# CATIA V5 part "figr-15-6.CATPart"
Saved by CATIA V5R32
Part number: Part1
Bounding box of the stored display mesh (mm): x -50 to 50, y -32.5 to 33.5, z -52 to 1
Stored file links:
  D:\PROJECTS\Project 2022\CATIA V5 6R 2022\Resources\Part Files\c15_catia_v5_6r2022_prt\figr-15-6.CATPart
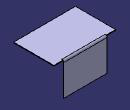
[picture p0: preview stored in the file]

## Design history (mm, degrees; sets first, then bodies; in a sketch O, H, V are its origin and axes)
SheetMetalParameters1: Thickness 1, BendRadius 2, KFactor 0.400515 {= log(min(100,max(20*SheetMetalParameters1.BendRadius,SheetMetalParameters1.Thickness)/SheetMetalParameters1.Thickness))/log(100)/2}, ReliefRadialLength 1, ReliefAxialLength 2, MinimumBendRadius 0
Body1 (main body)
  Sketch1 on xy-plane, origin (0, 0, 0), H (1, 0, 0), V (0, 1, 0)
    line L1 (-50, 32.5) -> (50, 32.5)
    line L2 (50, 32.5) -> (50, -32.5)
    line L3 (50, -32.5) -> (-50, -32.5)
    line L4 (-50, -32.5) -> (-50, 32.5)
    length L1 = 100
    length L2 = 65
    horizontal: L1 H, L3 H
    vertical: L2 V, L4 V
    symmetry: L4 L2 V, L1 L3 H
  Wall1: Thickness 1, Profile Sketch1
  d_NewWallOnEdge1: NewWallOnEdge_Edge edge [face of Wall1 | face of Wall1], NewWallOnEdge_Length 53, NewWallOnEdge_HeightLimitOffset 0, NewWallOnEdge_WidthOffset1 -15, NewWallOnEdge_WidthOffset2 -15, NewWallOnEdge_Angle 90, NewWallOnEdge_BendRadiusValue 2 {= SheetMetalParameters1.BendRadius}, NewWallOnEdge_BendTable SheetMetalParameters1, KFacteur 0.400515 {= log(min(100,max(20*d_NewWallOnEdge1.Radius,SheetMetalParameters1.Thickness)/SheetMetalParameters1.Thickness))/log(100)/2}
